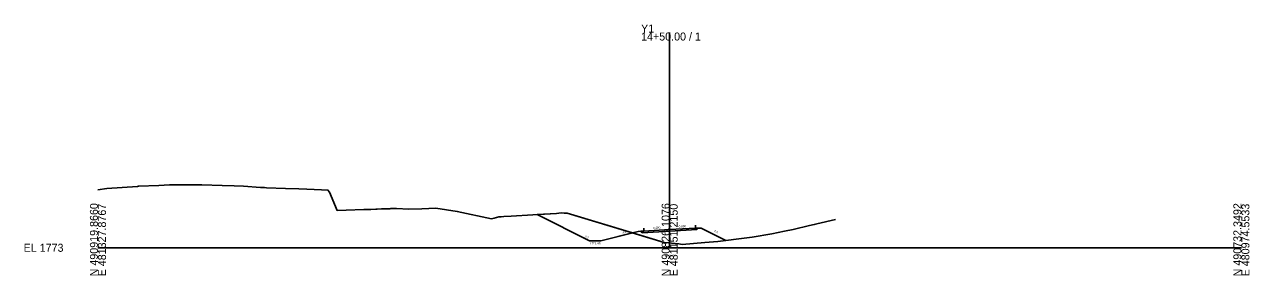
# Model space of a CAD drawing. Extents: x -26 to 403, y -10 to 6561.
# Drawn here: x -25.7 to 402.8, y 4490.3 to 4578.1 of the extents above; entities that cross this region are included whole.
import ezdxf

# ---------------------------------------------------------------- set-up
doc = ezdxf.new("R2010")
doc.units = 0
for name, color, linetype in [('Exist Cross Section Cell', 7, 'Continuous'), ('Exist XS Center Line Elevation Label', 7, 'Continuous'), ('Exist XS Ground Line', 7, 'Continuous'), ('Prop Road Sect_ Boring - Header (ID Tx)', 7, 'Continuous'), ('Prop Road Sect_ Material - Tx (Composite Desc)', 7, 'Continuous'), ('Prop XS Ditch Slope Text', 7, 'Continuous'), ('Prop XS Ditch Standard Text', 7, 'Continuous'), ('Prop XS EOT Tick Mark', 7, 'Continuous'), ('Prop XS Finish Grade', 7, 'Continuous'), ('Prop XS Finish Grade Earthwork', 7, 'Continuous'), ('Prop XS Finish Grade Pavement', 7, 'Continuous'), ('Prop XS Pvmt Edge Slope', 7, 'Continuous'), ('Prop XS SE Text', 7, 'Continuous'), ('Prop XS Side Slope Text', 7, 'Continuous'), ('Prop XS Subgrade Earthwork', 7, 'Continuous')]:
    doc.layers.add(name, color=color, linetype=linetype)

msp = doc.modelspace()

# ---------------------------------------------------------------- linework, layer by layer
at = {"layer": 'Exist Cross Section Cell'}
for p, q in [((200, 4500), (200, 4575.27)), ((0, 4500), (200, 4500)), ((200, 4500), (400, 4500))]:
    msp.add_line(p, q, dxfattribs=at)
at = {"layer": 'Exist XS Ground Line'}
msp.add_lwpolyline([(0, 4520.28), (3.15, 4520.69), (13.87, 4521.47), (14.19, 4521.49), (21.27, 4521.79), (25.02, 4521.98), (28.66, 4521.95), (35.53, 4521.96), (36.35, 4521.95), (43.46, 4521.81), (47.67, 4521.62), (50.86, 4521.59), (56.86, 4521.12), (58.25, 4521.04), (58.99, 4521.01), (65.65, 4520.77), (70.31, 4520.66), (73.05, 4520.52), (78.2, 4520.28), (80.45, 4520.15), (81.03, 4519.44), (83.73, 4512.99), (86.85, 4513.1), (93.06, 4513.33), (93.77, 4513.36), (95.41, 4513.42), (97.2, 4513.48), (97.73, 4513.5), (99.25, 4513.56), (99.61, 4513.57), (100.1, 4513.59), (101, 4513.62), (101.77, 4513.65), (102.07, 4513.66), (102.48, 4513.68), (103.12, 4513.7), (103.5, 4513.72), (104.45, 4513.75), (108.74, 4513.52), (113.28, 4513.65), (118.24, 4513.86), (125.72, 4512.7), (137.65, 4510.17), (138.66, 4510.36), (140.28, 4510.78), (141.04, 4510.83), (141.94, 4510.88), (144.53, 4511.1), (152.18, 4511.55), (160.37, 4512.03), (162.06, 4512.16), (163.04, 4512.15), (164.13, 4512.13), (198.02, 4501.84), (200, 4501.68), (200.62, 4501.63), (203.18, 4501.41), (204.43, 4501.16), (212.27, 4501.84), (216.81, 4502.16), (227.02, 4503.46), (228.84, 4503.69), (235.79, 4504.89), (240.16, 4505.75), (243.19, 4506.43), (248.88, 4507.73), (250.58, 4508.12), (251.49, 4508.34), (257.98, 4509.83)], dxfattribs=at)
at = {"layer": 'Prop Road Sect_ Boring - Header (ID Tx)'}
for points in [[(190.42, 4505.25), (189.91, 4505.76), (191, 4505.83)], [(209.98, 4506.87), (209.51, 4506.39), (209, 4506.91)]]:
    msp.add_lwpolyline(points, close=True, dxfattribs=at)
at = {"layer": 'Prop Road Sect_ Material - Tx (Composite Desc)'}
for points in [[(171.97, 4502.45), (153.61, 4511.63), (160.37, 4512.03), (162.06, 4512.16), (163.04, 4512.15), (164.13, 4512.13), (186.97, 4505.2), (175.97, 4502.45)], [(189, 4505.71), (186.97, 4505.2), (198.02, 4501.84), (200, 4501.68), (200.62, 4501.63), (203.18, 4501.41), (204.43, 4501.16), (212.27, 4501.84), (216.81, 4502.16), (219.62, 4502.51), (211, 4506.83), (209.98, 4506.87), (209.51, 4506.39), (200.03, 4505.83), (190.42, 4505.25), (189.91, 4505.76)]]:
    msp.add_lwpolyline(points, close=True, dxfattribs=at)
at = {"layer": 'Prop XS EOT Tick Mark'}
for p, q in [((191, 4505.83), (191, 4506.83)), ((209, 4506.91), (209, 4507.91))]:
    msp.add_line(p, q, dxfattribs=at)
at = {"layer": 'Prop XS Finish Grade'}
for p, q in [((191, 4505.83), (189.91, 4505.76)), ((209, 4506.91), (209.98, 4506.87))]:
    msp.add_line(p, q, dxfattribs=at)
at = {"layer": 'Prop XS Finish Grade Earthwork'}
for p, q in [((171.97, 4502.45), (153.61, 4511.63)), ((189, 4505.71), (175.97, 4502.45)), ((189, 4505.71), (189.91, 4505.76)), ((209.98, 4506.87), (211, 4506.83)), ((211, 4506.83), (219.62, 4502.51)), ((175.97, 4502.45), (171.97, 4502.45))]:
    msp.add_line(p, q, dxfattribs=at)
at = {"layer": 'Prop XS Finish Grade Pavement'}
for p, q in [((191, 4505.83), (200, 4506.37)), ((200, 4506.37), (209, 4506.91))]:
    msp.add_line(p, q, dxfattribs=at)
at = {"layer": 'Prop XS Pvmt Edge Slope'}
for p, q in [((191, 4505.83), (190.42, 4505.25)), ((209, 4506.91), (209.51, 4506.39))]:
    msp.add_line(p, q, dxfattribs=at)
at = {"layer": 'Prop XS Subgrade Earthwork'}
for p, q in [((190.42, 4505.25), (189.91, 4505.76)), ((190.42, 4505.25), (200.03, 4505.83)), ((200.03, 4505.83), (209.51, 4506.39)), ((209.98, 4506.87), (209.51, 4506.39))]:
    msp.add_line(p, q, dxfattribs=at)

# ---------------------------------------------------------------- texts
at = {"layer": 'Exist Cross Section Cell'}
for s, p in [('Y1', (190, 4575.27)), ('14+50.00 / 1', (190, 4572.47)), ('EL 1773', (-26, 4498.6))]:
    msp.add_text(s, height=2.8, dxfattribs=at).set_placement(p)
for s, p in [('N 490919.8660', (0, 4490)), ('E 481327.8767', (2.8, 4490)), ('N 490826.1076', (200, 4490)), ('E 481151.2150', (202.8, 4490)), ('N 490732.3492', (400, 4490)), ('E 480974.5533', (402.8, 4490))]:
    msp.add_text(s, height=2.8, rotation=90, dxfattribs=at).set_placement(p)
at = {"layer": 'Exist XS Center Line Elevation Label'}
msp.add_text('1774.68', height=0.75, dxfattribs=at).set_placement((198.34, 4496.89))
at = {"layer": 'Prop XS Ditch Slope Text'}
msp.add_text('4:1', height=0.75, rotation=14.0362, dxfattribs=at).set_placement((183.6, 4504.92))
at = {"layer": 'Prop XS Ditch Standard Text'}
msp.add_text('1775.45', height=0.75, dxfattribs=at).set_placement((172.03, 4501.16))
at = {"layer": 'Prop XS SE Text'}
for p in [(194.17, 4506.52), (203.17, 4507.06)]:
    msp.add_text('0.060', height=0.75, rotation=3.4336, dxfattribs=at).set_placement(p)
at = {"layer": 'Prop XS Side Slope Text'}
for p in [(170.21, 4503.73), (215.44, 4505.66)]:
    msp.add_text('2:1', height=0.75, rotation=333.4349, dxfattribs=at).set_placement(p)

doc.saveas('drawing.dxf')
